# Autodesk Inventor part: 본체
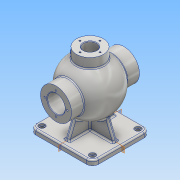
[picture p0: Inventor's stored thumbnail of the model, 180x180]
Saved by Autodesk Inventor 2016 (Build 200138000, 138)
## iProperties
Created: 2017-01
Part Number: 본체
Material: 알루미늄 6061
Document SubType Name: Modeling
Designer: Administrator
Density: 2.7 g/cm^3
Appearance: 알루미늄 - 평지
Mass: 1501.31 g
Surface Area: 1176.39 cm^2
Volume: 556.04 cm^3
Author: Administrator
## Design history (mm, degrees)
sketch "스케치1"
  geometry: L1 (0, 0)-(125, 0); L2 (125, 0)-(125, 115); L3 (125, 115)-(0, 115); L4 (0, 115)-(0, 0)
  constraints: 8 end point, 2 parallel, 1 horizontal, 1 perpendicular
  dimensions: "d0" = 125 distance of L3.end L2.end; "d1" = 115 distance of L2.end L1.end
extrude "돌출1" new body sketch "스케치1" distance "d2" = 10; taper "d3" = 0 deg
fillet "모깎기1" dims "d4" = 12
sketch "스케치2"
  geometry: L1 (62.5, 153.628)-(62.5, -34.735); L2 (-66.186, 57.5)-(185.77, 57.5); L3 (113, 115)-(12, 115) reference; L4 (0, 103)-(0, 12) reference; A1 r 12 centre (12, 103) between (12, 115) and (0, 103) reference; 2 further points
  constraints: 4 end point, 1 coincident, 1 horizontal, 1 vertical
  dimensions: "d5" = 57.5 distance between parallel lines of L2 L3; "d6" = 62.5 distance between parallel lines of L4 L1
hole "구멍1" sketch "스케치2" at (12, 103) diameter "d7" = 8; stored, may be unused: countersink angle "d11" = 90 deg, drill point angle "d13" = 118 deg; dims "d8" = 6, "d9" = 12, "d10" = 3, "d12" = 8
fillet "모깎기2" dims "d20" = 3
node "작업 평면3"
node "작업 평면4"
sketch "스케치4"
  geometry: L1 (85, -45.352)-(85, 154.07); L2 (0, 0)-(0, 91) reference; L3 (85, -22.5)-(116, -22.5); L4 (116, -22.5)-(116, 2.512); L5 (85, 113.5)-(116, 113.5); L6 (116, 113.5)-(116, 88.488); L7 (0, 91)-(0, 0) reference; L8 (0, 45.5)-(153.3, 45.5); L9 (85, -22.5)-(85, 113.5); A1 r 53 centre (85, 45.5) between (116, 2.512) and (116, 88.488); 1 further point
  constraints: 14 end point, 4 perpendicular, 4 point on line, 2 point on circle, 1 centre point, 1 collinear, 1 horizontal, 1 midpoint, 1 vertical
  dimensions: "d21" = 85 distance between parallel lines of L2 L1; "d22" = 31 horizontal distance of L1.start L3.end; "d23" = 31 distance from line of L1 L5.end; "d24" = 136 distance of L5.end L3.end; "d25" = 68 distance from line of L8 L5.end; "d26" = 106 diameter of A1
revolve "회전1" sketch "스케치4" stored, may be unused: angle "d27" = 90 deg
node "작업 평면5"
sketch "스케치5"
  geometry: C1 r 27 at (-62.5, 57.5); C2 r 13 at (-62.5, 57.5); 1 further point
  constraints: 2 centre point, 1 coincident
  dimensions: "d29" = 54 diameter of C1; "d32" = 26 diameter of C2
extrude "돌출2" join sketch "스케치5" stored distance "d30" = 10; taper "d31" = 0 deg
extrude "돌출3" cut sketch "스케치5" distance "d33" = 65; taper "d34" = 0 deg
sketch "스케치6"
  geometry: L1 (85, -54.348)-(85, 163.047); L2 (0, 91)-(0, 103) reference; L3 (0, 91)-(0, 0) reference; L4 (0, 45.5)-(163.738, 45.5); L5 (54, -22.5)-(116, -22.5) reference; L6 (102.5, -22.5)-(102.5, 6.222); L7 (54, 113.5)-(116, 113.5) reference; L8 (85, 58.5)-(85, 32.5) reference; L9 (102.5, -22.5)-(85, -22.5); L10 (85, -22.5)-(85, 113.5); L11 (103.5, 97.5)-(102.5, 97.5); L12 (103.5, 95.75)-(102.5, 95.75); L13 (103.5, 95.75)-(103.5, 97.5); L14 (102.5, 113.5)-(102.5, 97.5); L15 (102.5, 95.75)-(102.5, 84.778); A1 r 43 centre (85, 45.5) between (102.5, 6.222) and (102.5, 84.778); 1 further point
  constraints: 20 end point, 5 vertical, 4 midpoint, 2 perpendicular, 2 point on circle, 2 point on line, 1 centre point, 1 horizontal
  dimensions: "d35" = 85 distance between parallel lines of L2 L1; "d36" = 17.5 distance from line of L1 L6.start; "d37" = 17.5 distance from line of L1 L14.start; "d38" = 86 diameter of A1; "d39" = 16 distance between parallel lines of L7 L11; "d40" = 1.75 distance between parallel lines of L12 L11; "d41" = 18.5 distance between parallel lines of L1 L13
revolve "회전2" sketch "스케치6" stored, may be unused: angle "d42" = 90 deg
sketch "스케치7"
  geometry: L1 (10, 0)-(10, 91) reference; L2 (10, -2)-(44.109, 11.781); L3 (10, -2)-(72.654, -2); L4 (0, -12)-(7, -12) reference; L5 (10, 93)-(44.109, 79.219); L6 (10, 93)-(58.222, 93); L7 (7, 103)-(0, 103) reference; L8 (10, -2)-(10, 93); L9 (10, 97)-(10, 85) reference; A1 r 53 centre (85, 45.5) between (44.109, 79.219) and (44.109, 11.781)
  constraints: 10 end point, 2 horizontal, 2 point on circle, 2 point on line, 1 centre point, 1 collinear
  dimensions: "d43" = 22 deg angle of L3 L2; "d44" = 10 distance from line of L4 L2.start; "d45" = 22 deg angle of L5 L6; "d46" = 10 distance from line of L7 L5.start
extrude "돌출4" join sketch "스케치7" stored distance "d47" = 8; taper "d48" = 0 deg
sketch "스케치8"
  geometry: L1 (0, 10)-(101, 10) reference; L2 (-2, 10)-(13.121, 47.426); L3 (-12, 0)-(-12, 7) reference; L4 (103, 10)-(87.879, 47.426); L5 (113, 7)-(113, 0) reference; L6 (-2, 10)-(103, 10); L7 (101, 7)-(0, 7) reference; A1 r 53 centre (50.5, 85) between (23.5, 130.607) and (77.5, 130.607) reference; A2 r 53 centre (50.5, 85) between (13.121, 47.426) and (87.879, 47.426)
  constraints: 6 end point, 4 point on circle, 2 point on line, 1 centre point, 1 parallel
  dimensions: "d49" = 68 deg angle of L1 L2; "d50" = 10 distance from line of L2.start L3; "d51" = 68 deg angle of L1 L4; "d52" = 10 distance from line of L5 L4.start
extrude "돌출5" join sketch "스케치8" stored distance "d53" = 8; taper "d54" = 0 deg
sketch "스케치9"
  geometry: 2 further points
hole "구멍2" sketch "스케치9" at (0, 22.5) diameter "d57" = 3.242; stored, may be unused: countersink angle "d61" = 90 deg, drill point angle "d63" = 118 deg; dims "d58" = 12, "d59" = 4, "d60" = 3, "d62" = 15
sketch "스케치10"
  geometry: C1 r 17.5 at (0, 0) reference; 2 further points
hole "구멍3" sketch "스케치10" at (0, -24) diameter "d70" = 3.242; stored, may be unused: countersink angle "d74" = 90 deg, drill point angle "d76" = 118 deg; dims "d71" = 16, "d72" = 4, "d73" = 3, "d75" = 19
sketch "스케치11"
  geometry: 2 further points
hole "구멍4" sketch "스케치11" at (0.113, -20) diameter "d81" = 3.242; stored, may be unused: countersink angle "d85" = 90 deg, drill point angle "d87" = 118 deg; dims "d82" = 9, "d83" = 4, "d84" = 3, "d86" = 11
chamfer "모따기1" distance "d91" = 1; stored, may be unused: second distance "d92" = 2, angle "d93" = 45 deg
chamfer "모따기2" distance "d94" = 1; stored, may be unused: second distance "d95" = 2, angle "d96" = 45 deg
fillet "모깎기3" dims "d97" = 3
fillet "모깎기4" dims "d98" = 3
sketch "스케치13"
  geometry: L1 (135.763, 51.682)-(135.763, 39.318); L2 (135.763, 39.318)-(144.237, 39.318); L3 (144.237, 39.318)-(144.237, 51.682); L4 (144.237, 51.682)-(135.763, 51.682); L5 (150, 18.5)-(150, 72.5) reference; 3 further points
  constraints: 2 midpoint, 2 other
  dimensions: "d99" = 10 distance from line of L5 point (140, 39.318); "d101" = 27 vertical distance of L5.end point (144.237, 45.5)
feature "엠보싱1" sketch "스케치13" dims "d0" = 125, "d1" = 115, "d13" = 118 deg, "d102" = 0.5, "d103" = 0
node "솔리드1"
pattern_linear "직사각형 패턴1" dims "d16" = 91, "d19" = 101
pattern_circular "원형 패턴1" dims angle "d65" = 360 deg
pattern_circular "원형 패턴2" dims angle "d78" = 360 deg
pattern_circular "원형 패턴3" dims angle "d89" = 360 deg
